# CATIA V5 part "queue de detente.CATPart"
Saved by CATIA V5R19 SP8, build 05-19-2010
Part number: queue de détente
Bounding box of the stored display mesh (mm): x 0 to 10, y -16.366 to 7.522, z -23.308 to 2.963
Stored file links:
  E:\Catia parts\GLOCK\Poignée\queue de detente.CATPart
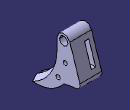
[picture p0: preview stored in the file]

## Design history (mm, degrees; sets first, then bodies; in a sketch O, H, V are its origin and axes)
Body1 (main body)
  Solid1: solid without history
